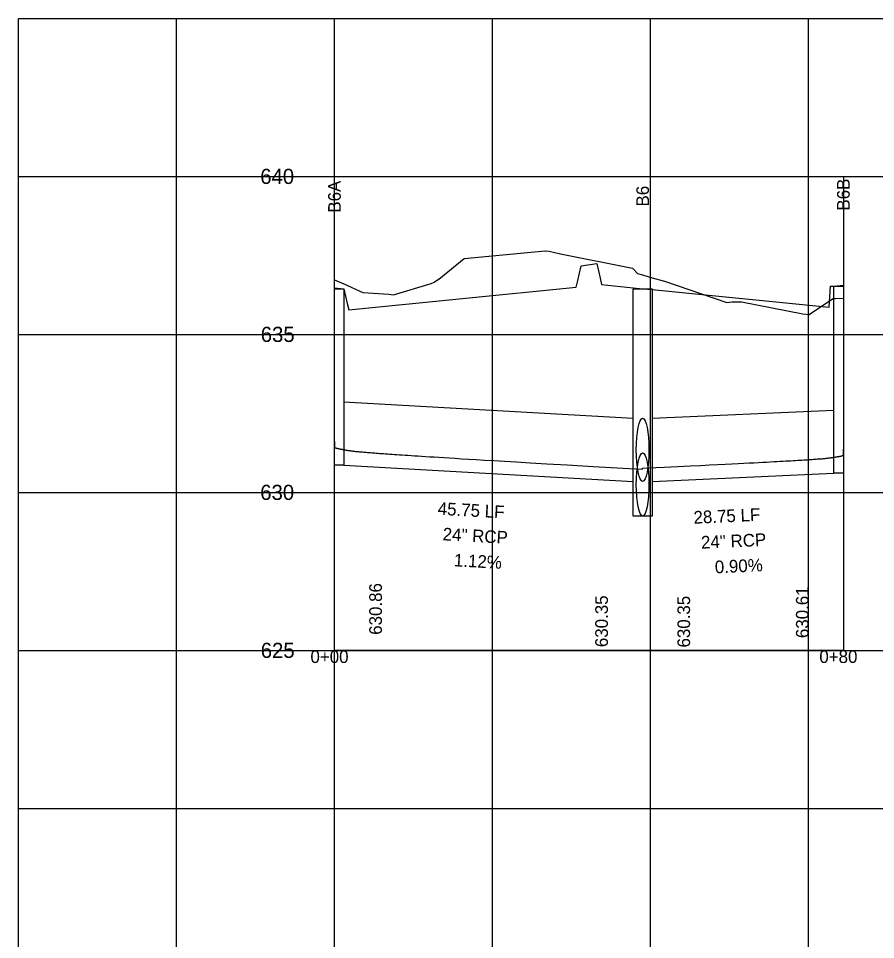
# Model space of a CAD drawing. Extents: x 2254979 to 2278074, y 13790855 to 13792793.
# Drawn here: x 2277749.4 to 2277885, y 13792645.5 to 13792791.3 of the extents above; entities that cross this region are included whole.
import ezdxf

# ---------------------------------------------------------------- set-up
doc = ezdxf.new("R2010")
doc.units = 0
for name, color, linetype in [('blank4', 7, 'Continuous'), ('BORD_grid_bottom_major_5int', 7, 'Continuous'), ('D_DRN_PROF_HGL', 7, 'Continuous'), ('D_PROF_1', 7, 'Continuous'), ('D_PROF_NOTES_1', 7, 'Continuous'), ('Default', 7, 'Continuous'), ('Drain_PipeInside', 7, 'Continuous'), ('E_Terrain', 7, 'Continuous'), ('Inlet', 7, 'Continuous'), ('z - Construction', 7, 'Continuous')]:
    doc.layers.add(name, color=color, linetype=linetype)

msp = doc.modelspace()

# ---------------------------------------------------------------- linework, layer by layer
at = {"layer": 'blank4'}
msp.add_lwpolyline([(2277799.4, 13792691.27), (2277799.4, 13792766.27), (2277879.9, 13792766.27), (2277879.9, 13792691.27)], close=True, dxfattribs=at)
at = {"layer": 'BORD_grid_bottom_major_5int'}
for p, q in [((2277749.4, 13792791.27), (2278074.4, 13792791.27)), ((2277749.4, 13792491.27), (2277749.4, 13792791.27)), ((2277774.4, 13792491.27), (2277774.4, 13792791.27)), ((2277799.4, 13792491.27), (2277799.4, 13792791.27)), ((2277824.4, 13792491.27), (2277824.4, 13792791.27)), ((2277849.4, 13792491.27), (2277849.4, 13792791.27)), ((2277874.4, 13792491.27), (2277874.4, 13792791.27)), ((2277749.4, 13792766.27), (2278074.4, 13792766.27)), ((2277749.4, 13792741.27), (2278074.4, 13792741.27)), ((2277749.4, 13792716.27), (2278074.4, 13792716.27)), ((2277749.4, 13792691.27), (2278074.4, 13792691.27)), ((2277749.4, 13792666.27), (2278074.4, 13792666.27))]:
    msp.add_line(p, q, dxfattribs=at)
at = {"layer": 'D_DRN_PROF_HGL'}
msp.add_line((2277848.15, 13792719.93), (2277848.15, 13792720.1), dxfattribs=at)
for points in [[(2277799.4, 13792724.33), (2277799.4, 13792723.42), (2277799.41, 13792723.41), (2277799.41, 13792723.41), (2277799.41, 13792723.4), (2277799.41, 13792723.4), (2277799.42, 13792723.39), (2277799.43, 13792723.39), (2277799.43, 13792723.38), (2277799.44, 13792723.38), (2277799.45, 13792723.37), (2277799.46, 13792723.36), (2277799.48, 13792723.36), (2277799.49, 13792723.35), (2277799.51, 13792723.34), (2277799.52, 13792723.34), (2277799.54, 13792723.33), (2277799.56, 13792723.32), (2277799.58, 13792723.31), (2277799.6, 13792723.31), (2277799.63, 13792723.3), (2277799.65, 13792723.29), (2277799.68, 13792723.28), (2277799.71, 13792723.28), (2277799.74, 13792723.27), (2277799.77, 13792723.26), (2277799.8, 13792723.25), (2277799.84, 13792723.24), (2277799.87, 13792723.23), (2277799.91, 13792723.22), (2277799.95, 13792723.21), (2277800, 13792723.2), (2277800.04, 13792723.19), (2277800.09, 13792723.18), (2277800.14, 13792723.17), (2277800.19, 13792723.16), (2277800.24, 13792723.15), (2277800.29, 13792723.14), (2277800.35, 13792723.13), (2277800.41, 13792723.12), (2277800.47, 13792723.1), (2277800.54, 13792723.09), (2277800.6, 13792723.08), (2277800.67, 13792723.07), (2277800.74, 13792723.05), (2277800.82, 13792723.04), (2277800.9, 13792723.03), (2277800.98, 13792723.01), (2277801.06, 13792723), (2277801.14, 13792722.98), (2277801.23, 13792722.97), (2277801.33, 13792722.95), (2277801.42, 13792722.94), (2277801.52, 13792722.92), (2277801.62, 13792722.91), (2277801.73, 13792722.89), (2277801.84, 13792722.87), (2277801.95, 13792722.85), (2277802.07, 13792722.84), (2277802.19, 13792722.82), (2277802.32, 13792722.8), (2277802.45, 13792722.78), (2277802.59, 13792722.77), (2277802.73, 13792722.76), (2277802.87, 13792722.74), (2277803.02, 13792722.73), (2277803.18, 13792722.71), (2277803.34, 13792722.7), (2277803.5, 13792722.69), (2277803.67, 13792722.67), (2277803.85, 13792722.66), (2277804.04, 13792722.64), (2277804.23, 13792722.63), (2277804.43, 13792722.61), (2277804.63, 13792722.59), (2277804.85, 13792722.58), (2277805.07, 13792722.56), (2277805.3, 13792722.54), (2277805.54, 13792722.52), (2277805.78, 13792722.5), (2277806.04, 13792722.48), (2277806.31, 13792722.46), (2277806.59, 13792722.44), (2277806.88, 13792722.42), (2277807.18, 13792722.4), (2277807.49, 13792722.38), (2277807.82, 13792722.35), (2277808.16, 13792722.33), (2277808.51, 13792722.31), (2277808.89, 13792722.28), (2277809.28, 13792722.25), (2277809.68, 13792722.22), (2277810.11, 13792722.2), (2277810.56, 13792722.17), (2277811.03, 13792722.13), (2277811.53, 13792722.1), (2277812.05, 13792722.07), (2277812.6, 13792722.03), (2277813.19, 13792721.99), (2277813.81, 13792721.95), (2277814.46, 13792721.91), (2277815.16, 13792721.87), (2277815.91, 13792721.82), (2277816.71, 13792721.77), (2277817.57, 13792721.72), (2277818.5, 13792721.66), (2277819.5, 13792721.6), (2277820.6, 13792721.53), (2277821.8, 13792721.46), (2277823.13, 13792721.38), (2277824.61, 13792721.29), (2277826.27, 13792721.19), (2277828.17, 13792721.08), (2277830.38, 13792720.95), (2277833, 13792720.8), (2277836.2, 13792720.62), (2277840.32, 13792720.38), (2277846.02, 13792720.06), (2277848.15, 13792719.93)], [(2277848.15, 13792720.1), (2277848.91, 13792720.14), (2277851.56, 13792720.27), (2277853.76, 13792720.37), (2277855.65, 13792720.46), (2277857.3, 13792720.54), (2277858.75, 13792720.61), (2277860.05, 13792720.68), (2277861.22, 13792720.73), (2277862.28, 13792720.79), (2277863.25, 13792720.84), (2277864.15, 13792720.88), (2277864.98, 13792720.92), (2277865.74, 13792720.96), (2277866.45, 13792721), (2277867.12, 13792721.04), (2277867.75, 13792721.07), (2277868.33, 13792721.1), (2277868.88, 13792721.13), (2277869.4, 13792721.16), (2277869.89, 13792721.19), (2277870.36, 13792721.21), (2277870.8, 13792721.24), (2277871.22, 13792721.26), (2277871.61, 13792721.28), (2277871.99, 13792721.31), (2277872.35, 13792721.33), (2277872.69, 13792721.35), (2277873.02, 13792721.37), (2277873.33, 13792721.39), (2277873.63, 13792721.4), (2277873.91, 13792721.42), (2277874.19, 13792721.44), (2277874.45, 13792721.46), (2277874.7, 13792721.47), (2277874.94, 13792721.49), (2277875.17, 13792721.5), (2277875.39, 13792721.52), (2277875.6, 13792721.53), (2277875.8, 13792721.55), (2277876, 13792721.56), (2277876.18, 13792721.58), (2277876.36, 13792721.59), (2277876.53, 13792721.6), (2277876.7, 13792721.61), (2277876.86, 13792721.63), (2277877.01, 13792721.64), (2277877.16, 13792721.66), (2277877.3, 13792721.68), (2277877.43, 13792721.7), (2277877.56, 13792721.71), (2277877.69, 13792721.73), (2277877.81, 13792721.74), (2277877.92, 13792721.76), (2277878.03, 13792721.77), (2277878.14, 13792721.79), (2277878.24, 13792721.8), (2277878.34, 13792721.82), (2277878.43, 13792721.83), (2277878.52, 13792721.84), (2277878.61, 13792721.86), (2277878.69, 13792721.87), (2277878.77, 13792721.88), (2277878.84, 13792721.89), (2277878.91, 13792721.9), (2277878.98, 13792721.92), (2277879.05, 13792721.93), (2277879.11, 13792721.94), (2277879.17, 13792721.95), (2277879.23, 13792721.96), (2277879.28, 13792721.97), (2277879.33, 13792721.98), (2277879.38, 13792721.99), (2277879.43, 13792722), (2277879.47, 13792722), (2277879.51, 13792722.01), (2277879.55, 13792722.02), (2277879.59, 13792722.03), (2277879.62, 13792722.04), (2277879.65, 13792722.05), (2277879.68, 13792722.05), (2277879.71, 13792722.06), (2277879.73, 13792722.07), (2277879.76, 13792722.08), (2277879.78, 13792722.08), (2277879.8, 13792722.09), (2277879.82, 13792722.1), (2277879.83, 13792722.1), (2277879.85, 13792722.11), (2277879.86, 13792722.12), (2277879.87, 13792722.12), (2277879.88, 13792722.13), (2277879.89, 13792722.13), (2277879.9, 13792722.14), (2277879.9, 13792722.14), (2277879.9, 13792722.15), (2277879.9, 13792722.15), (2277879.9, 13792722.16), (2277879.9, 13792723.09)]]:
    msp.add_lwpolyline(points, dxfattribs=at)
at = {"layer": 'D_PROF_1'}
msp.add_lwpolyline([(2277799.4, 13792748.64), (2277800.9, 13792748.49), (2277800.9, 13792748.49), (2277801.43, 13792746.17), (2277801.65, 13792745.15), (2277837.65, 13792748.75), (2277837.88, 13792749.77), (2277838.4, 13792752.09), (2277840.9, 13792752.49), (2277841.43, 13792750.17), (2277841.65, 13792749.15), (2277846.65, 13792748.65), (2277846.65, 13792748.65), (2277848.15, 13792748.5), (2277848.15, 13792748.5), (2277849.65, 13792748.35), (2277849.65, 13792748.35), (2277877.65, 13792745.55), (2277877.88, 13792748.89), (2277878.4, 13792748.89), (2277878.4, 13792748.89), (2277879.9, 13792749.04)], dxfattribs=at)
at = {"layer": 'Drain_PipeInside'}
for p, q in [((2277800.9, 13792730.57), (2277846.65, 13792728)), ((2277849.65, 13792728), (2277878.4, 13792729.3)), ((2277800.9, 13792720.57), (2277846.65, 13792718)), ((2277849.65, 13792718), (2277878.4, 13792719.3))]:
    msp.add_line(p, q, dxfattribs=at)
for centre in [(2277848.15, 13792723), (2277848.15, 13792717.52)]:
    msp.add_ellipse(centre, major_axis=(0, 5), ratio=0.2, dxfattribs=at)
at = {"layer": 'E_Terrain'}
msp.add_lwpolyline([(2277799.4, 13792749.92), (2277800.9, 13792749.25), (2277800.9, 13792749.25), (2277803.87, 13792747.92), (2277808.01, 13792747.61), (2277808.72, 13792747.55), (2277814.69, 13792749.32), (2277815.19, 13792749.55), (2277815.85, 13792750.03), (2277815.89, 13792750.03), (2277819.9, 13792753.27), (2277831.06, 13792754.33), (2277832.76, 13792754.47), (2277832.81, 13792754.45), (2277832.86, 13792754.47), (2277833.38, 13792754.43), (2277835.17, 13792754.02), (2277846.54, 13792751.74), (2277846.65, 13792751.62), (2277846.65, 13792751.62), (2277847.36, 13792750.9), (2277848.15, 13792750.67), (2277848.15, 13792750.67), (2277849.65, 13792750.23), (2277849.65, 13792750.23), (2277851.61, 13792749.67), (2277861.47, 13792746.31), (2277862.33, 13792746.43), (2277863.76, 13792746.44), (2277873.47, 13792744.5), (2277874.49, 13792744.42), (2277878.32, 13792746.99), (2277878.4, 13792746.97), (2277878.4, 13792746.97), (2277878.64, 13792746.93), (2277879.9, 13792747)], dxfattribs=at)
at = {"layer": 'Inlet'}
for points in [[(2277799.4, 13792748.49), (2277800.9, 13792748.49), (2277800.9, 13792720.57), (2277799.4, 13792720.57)], [(2277846.65, 13792748.5), (2277849.65, 13792748.5), (2277849.65, 13792712.52), (2277846.65, 13792712.52)], [(2277878.4, 13792748.89), (2277879.9, 13792748.89), (2277879.9, 13792719.3), (2277878.4, 13792719.3)]]:
    msp.add_lwpolyline(points, close=True, dxfattribs=at)
at = {"layer": 'z - Construction'}
for p, q in [((2277799.4, 13792741.27), (2277879.9, 13792741.27)), ((2277799.4, 13792716.27), (2277879.9, 13792716.27))]:
    msp.add_line(p, q, dxfattribs=at)

# ---------------------------------------------------------------- texts
at = {"layer": 'D_PROF_NOTES_1'}
for s, rotation, p in [('B6A', 90, (2277800.4, 13792760.53)), ('B6B', 90, (2277880.9, 13792760.86)), ('B6', 90, (2277849.15, 13792761.51)), ('45.75 LF', 356.791, (2277815.69, 13792712.74)), ('28.75 LF', 2.589, (2277856.24, 13792711.3)), ('24" RCP', 356.791, (2277816.47, 13792708.69)), ('24" RCP', 2.589, (2277857.43, 13792707.35)), ('1.12%', 356.791, (2277818.25, 13792704.58)), ('0.90%', 2.589, (2277859.61, 13792703.45)), ('630.86', 90, (2277806.9, 13792693.73)), ('630.61', 90, (2277874.4, 13792693.21)), ('630.35', 90, (2277842.65, 13792691.78)), ('630.35', 90, (2277855.65, 13792691.72))]:
    msp.add_text(s, height=2, rotation=rotation, dxfattribs=at).set_placement(p)
at = {"layer": 'Default'}
for s, height, p in [('640', 2.4, (2277787.66, 13792765.07)), ('635', 2.4, (2277787.74, 13792740.07)), ('630', 2.4, (2277787.66, 13792715.07)), ('625', 2.4, (2277787.74, 13792690.07)), ('0+00', 2, (2277795.6, 13792689.27)), ('0+80', 2, (2277876.1, 13792689.27))]:
    msp.add_text(s, height=height, dxfattribs=at).set_placement(p)

doc.saveas('drawing.dxf')
